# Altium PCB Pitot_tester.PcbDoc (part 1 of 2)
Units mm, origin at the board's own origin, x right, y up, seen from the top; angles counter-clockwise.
Board outline 94.03 x 112.06 mm, 2 copper layers (Top Layer, Bottom Layer), stack 1.658 mm thick; 71 components, 60 nets, 466 pads, 349 vias.
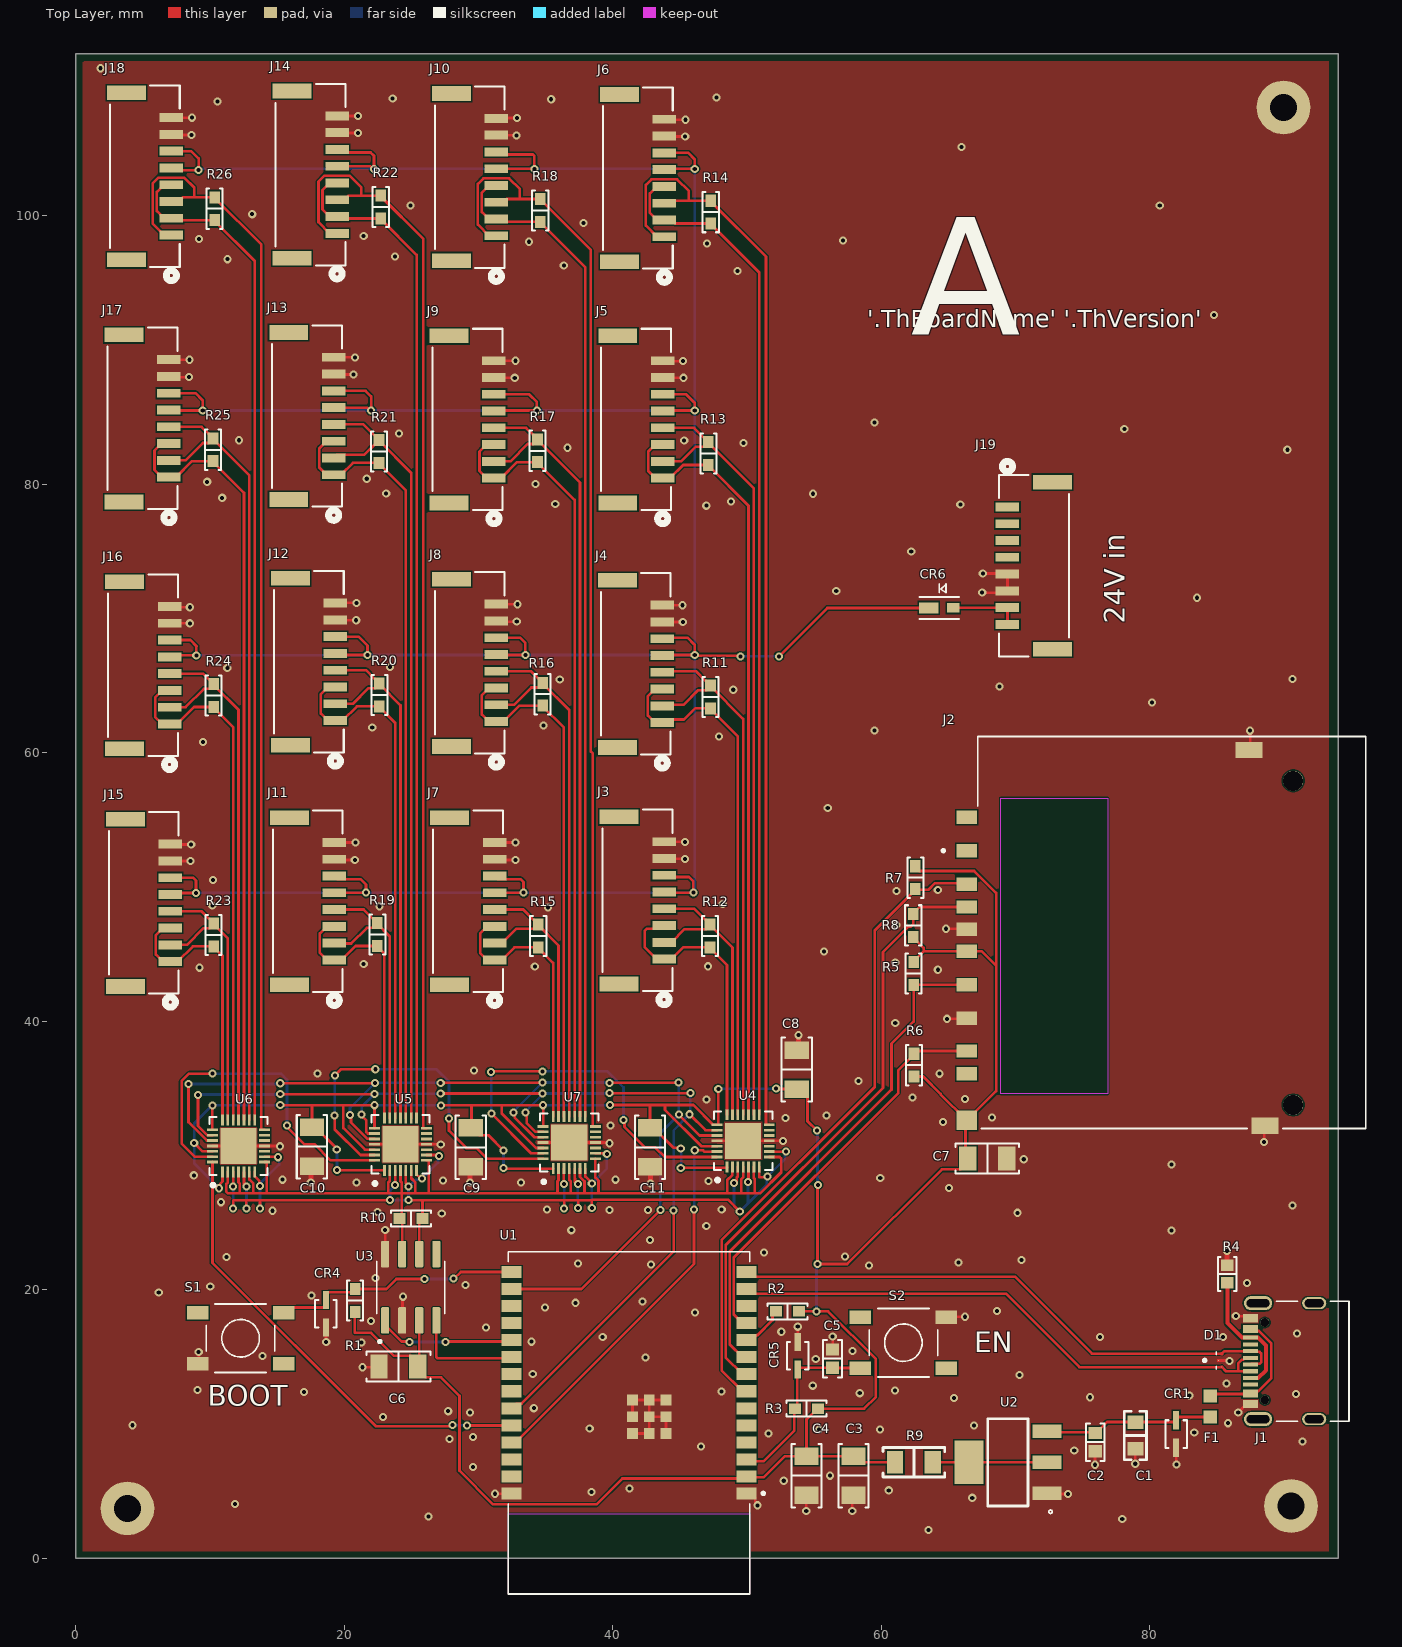
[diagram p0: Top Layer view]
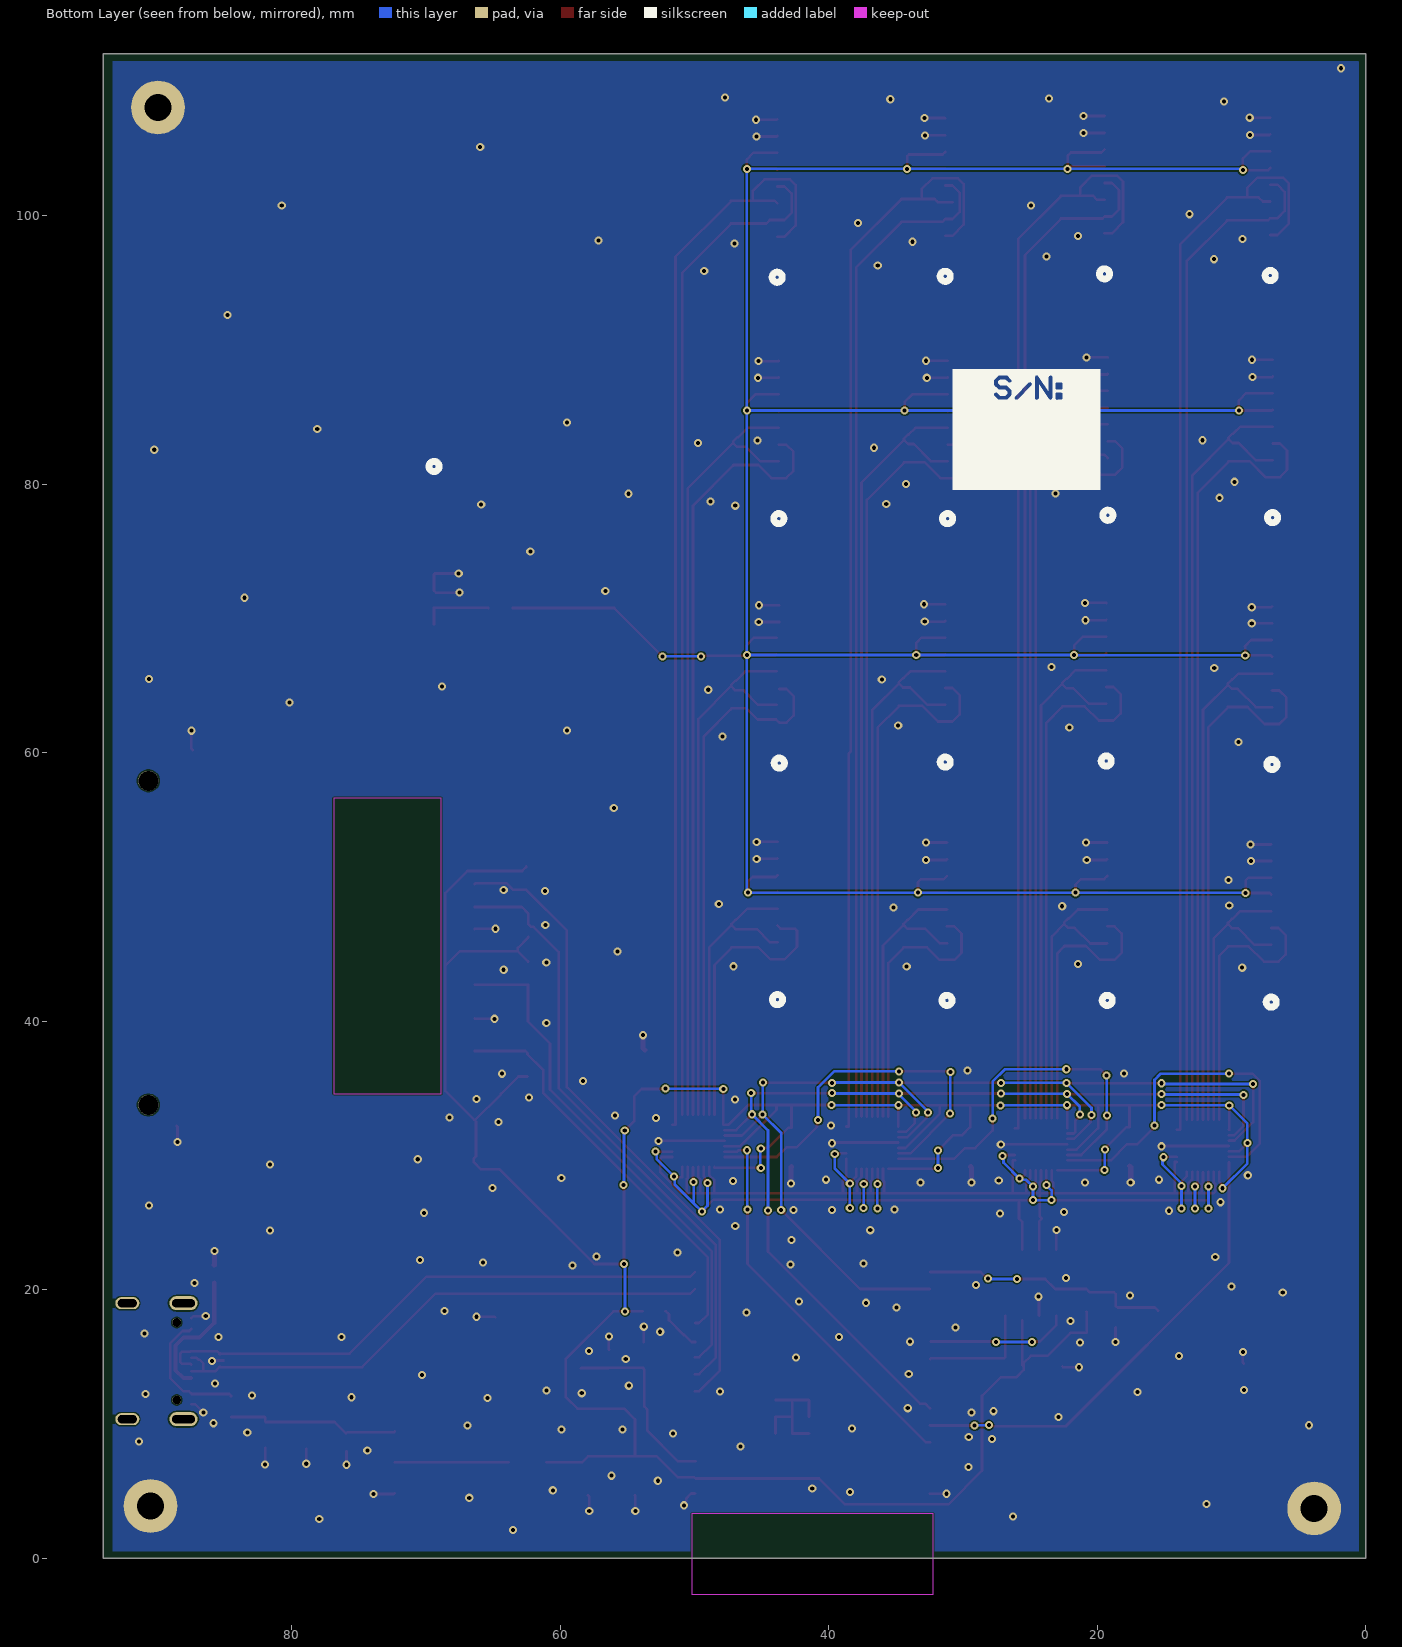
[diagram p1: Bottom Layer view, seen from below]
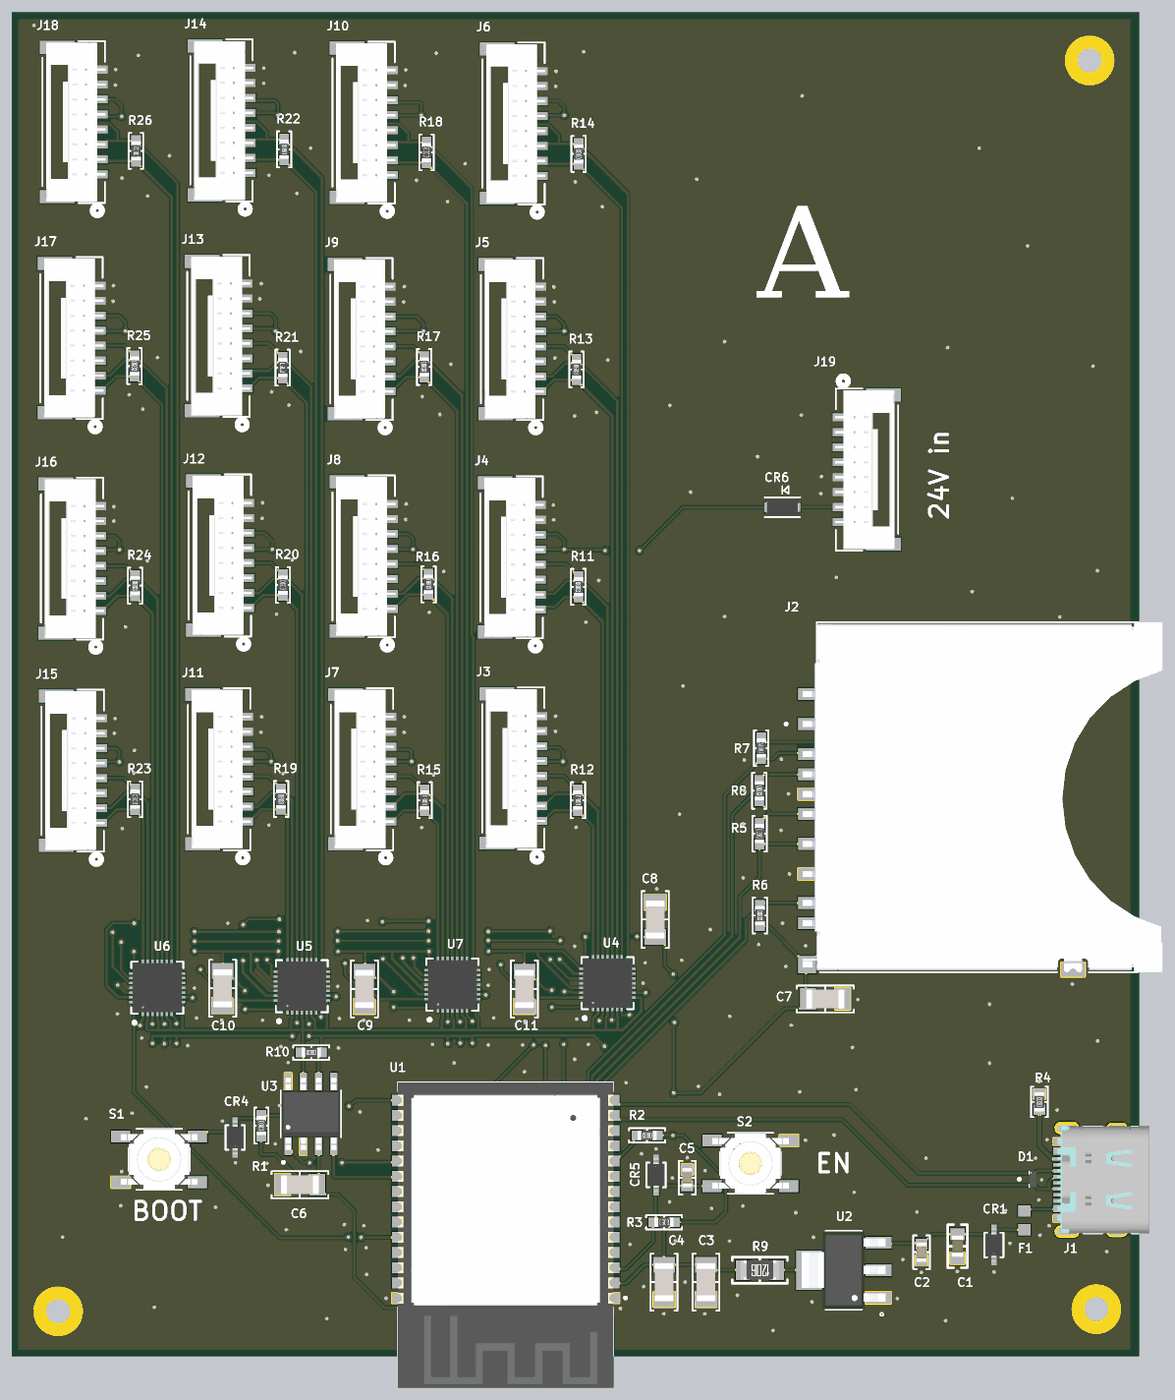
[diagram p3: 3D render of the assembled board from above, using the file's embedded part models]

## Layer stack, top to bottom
Top Solder: solder mask 0.0102, Solder Resist, Dk 3.5
Top Layer: signal copper 0.047
Dielectric 1: dielectric 1.564, FR-4, Dk 4.4
Bottom Layer: signal copper 0.047
Bottom Solder: solder mask 0.0102, Solder Resist, Dk 3.5

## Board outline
0,0 0,112.065 94.031,112.065 94.031,0

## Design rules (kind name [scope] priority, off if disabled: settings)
BoardOutlineClearance [All] p1: gap=0.4 ignorepadtopadclearanceinfootprint=FALSE
Clearance [All] p1: gap=0.1 ignorepadtopadclearanceinfootprint=FALSE
DiffPairsRouting [All] p1: maxlimit=0.5 minlimit=0.2 mostfreqgap=0.2 toplayer_minwidth=0.2 toplayer_maxwidth=0.2 toplayer_prefwidth=0.2 bottomlayer_minwidth=0.2 bottomlayer_maxwidth=0.2 bottomlayer_prefwidth=0.2 maxuncoupledlength=20
HoleSize [All] p1: absolutevalues=TRUE maxlimit=6.4 minlimit=0.2 maxpercent=80.000 minpercent=20.000
HoleToHoleClearance [All] p1: gap=0.45 allowstackedmicrovias=TRUE
MinimumAnnularRing [All] p1: minimumring=0.15
MinimumSolderMaskSliver [All] p1: minsoldermaskwidth=0.1
PolygonConnect [All] p1: connectstyle=Direct reliefconductorwidth=0.254 reliefentries=4 polygonreliefangle="90 Angle" airgapwidth=0.254
RoutingVias [All] p1: holewidth=0.3 width=0.6 viastyle="Through Hole" minholewidth=0.3 minwidth=0.5 maxholewidth=6.3 maxwidth=999
SilkToSilkClearance [All] p1: silktosilkclearance=0.2
SilkToSolderMaskClearance [IsPad] p1: minsilkscreentomaskgap=0.1 clearancetoexposedcopper=TRUE
SolderMaskExpansion SolderMaskExpansion_VIA [IsVia] p1: expansion=0.07 istentingtop=TRUE
SolderMaskExpansion [All] p2: expansion=0.07 istentingtop=FALSE
SupplyNets "Schematic Supply Nets_3" [InNet('+28')] p1: voltage=0.000
SupplyNets "Schematic Supply Nets_2" [InNet('+3.3')] p2: voltage=0.000
SupplyNets "Schematic Supply Nets_1" [InNet('+5')] p3: voltage=0.000
SupplyNets "Schematic Supply Nets" [InNet('GND')] p4: voltage=0.000
UnRoutedNet [All] p1: checkbadconnections=TRUE
Width [All] p1: maxlimit=999 minlimit=0.2 preferedwidth=0.2
23 further rules are at their usual default settings.

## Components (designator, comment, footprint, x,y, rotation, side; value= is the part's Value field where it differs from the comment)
C1 "10 µF" "MURATA GRM188 0603_1608" 78.932,9.142 r90 top
C2 "0.1 µF" "CAP 0603_1608" 75.932,8.642 r90 top
C3 "10 µF" "CAP 1206_3216 - 0.8MM" 57.932,6.142 r90 top
C4 "10 µF" "CAP 1206_3216 - 0.8MM" 54.432,6.142 r90 top
C5 "1 µF" "CAP 0603_1608" 56.363,14.859 r90 top
C6 "10 µF" "CAP 1206_3216 - 0.8MM" 24.028,14.275 r0 top
C7 "10 µF" "CAP 1206_3216 - 0.8MM" 67.894,29.769 r180 top
C8 "10 µF" "CAP 1206_3216 - 0.8MM" 53.696,36.398 r90 top
C9 "10 µF" "CAP 1206_3216 - 0.8MM" 29.413,30.607 r270 top
C10 "10 µF" "CAP 1206_3216 - 0.8MM" 17.577,30.658 r270 top
C11 "10 µF" "CAP 1206_3216 - 0.8MM" 42.774,30.607 r270 top
CR1 "PESD5V0U1BA_1" SOD323_NXP 81.966,9.246 r90 top
CR4 "PESD5V0U1BA_1" SOD323_NXP 18.618,18.212 r90 top
CR5 "PESD5V0U1BA_1" SOD323_NXP 53.772,15.088 r270 top
CR6 "MSS1P6-M389A" DIODE_MSP3V3_VIS 64.313,70.79 r0 top
D1 "ESD122DMYR" DIO_ESD122DMYR 85.242,14.732 r0 top
F1 "0603L100SLYR" FUSC1608X100N 84.506,11.301 r90 top
J1 "12402012E212A" AMPHENOL_12402012E212A 92.25,14.676 r90 top
J2 "GSD09002SDEU" AMPHENOL_GSD09002SDEU 90.68,46.612 r0 top
J3 "BM08B-GHS-TBT" CONN_BM08B-GHS-TBT_JST 41.838,49.003 r270 top
J4 "BM08B-GHS-TBT" CONN_BM08B-GHS-TBT_JST 41.707,66.624 r270 top
J5 "BM08B-GHS-TBT" CONN_BM08B-GHS-TBT_JST 41.737,84.835 r270 top
J6 "BM08B-GHS-TBT" CONN_BM08B-GHS-TBT_JST 41.859,102.819 r270 top
J7 "BM08B-GHS-TBT" CONN_BM08B-GHS-TBT_JST 29.21,48.946 r270 top
J8 "BM08B-GHS-TBT" CONN_BM08B-GHS-TBT_JST 29.342,66.7 r270 top
J9 "BM08B-GHS-TBT" CONN_BM08B-GHS-TBT_JST 29.164,84.835 r270 top
J10 "BM08B-GHS-TBT" CONN_BM08B-GHS-TBT_JST 29.342,102.889 r270 top
J11 "BM08B-GHS-TBT" CONN_BM08B-GHS-TBT_JST 17.272,48.946 r270 top
J12 "BM08B-GHS-TBT" CONN_BM08B-GHS-TBT_JST 17.348,66.777 r270 top
J13 "BM08B-GHS-TBT" CONN_BM08B-GHS-TBT_JST 17.226,85.089 r270 top
J14 "BM08B-GHS-TBT" CONN_BM08B-GHS-TBT_JST 17.475,103.073 r270 top
J15 "BM08B-GHS-TBT" CONN_BM08B-GHS-TBT_JST 5.055,48.819 r270 top
J16 "BM08B-GHS-TBT" CONN_BM08B-GHS-TBT_JST 5.004,66.523 r270 top
J17 "BM08B-GHS-TBT" CONN_BM08B-GHS-TBT_JST 4.953,84.912 r270 top
J18 "BM08B-GHS-TBT" CONN_BM08B-GHS-TBT_JST 5.131,102.946 r270 top
J19 "BM08B-GHS-TBT" CONN_BM08B-GHS-TBT_JST 71.374,73.939 r90 top
R1 "10 kOhms" "YAGEO RES 0603_1608" 20.803,19.202 r270 top
R2 "10 kOhms" "YAGEO RES 0603_1608" 53.01,18.39 r180 top
R3 "10 kOhms" "YAGEO RES 0603_1608" 54.432,11.142 r0 top
R4 "5.1 kOhms" "RES 0603_1608" 85.776,21.184 r90 top
R5 "10 kOhms" "YAGEO RES 0603_1608" 62.408,43.561 r90 top
R6 "10 kOhms" "YAGEO RES 0603_1608" 62.433,36.728 r270 top
R7 "10 kOhms" "YAGEO RES 0603_1608" 62.535,50.698 r90 top
R8 "10 kOhms" "YAGEO RES 0603_1608" 62.382,47.142 r270 top
R9 "500 mOhms" "RES 1206_3216" 62.432,7.142 r180 top
R10 "120 Ohms" "YAGEO RES 0603_1608" 24.968,25.298 r180 top
R11 "120 Ohms" "YAGEO RES 0603_1608" 47.269,64.16 r270 top
R12 "120 Ohms" "YAGEO RES 0603_1608" 47.244,46.355 r270 top
R13 "120 Ohms" "YAGEO RES 0603_1608" 47.117,82.296 r270 top
R14 "120 Ohms" "YAGEO RES 0603_1608" 47.295,100.279 r90 top
R15 "120 Ohms" "YAGEO RES 0603_1608" 34.442,46.355 r270 top
R16 "120 Ohms" "YAGEO RES 0603_1608" 34.773,64.364 r270 top
R17 "120 Ohms" "YAGEO RES 0603_1608" 34.392,82.499 r270 top
R18 "120 Ohms" "YAGEO RES 0603_1608" 34.595,100.406 r90 top
R19 "120 Ohms" "YAGEO RES 0603_1608" 22.454,46.457 r270 top
R20 "120 Ohms" "YAGEO RES 0603_1608" 22.606,64.313 r270 top
R21 "120 Ohms" "YAGEO RES 0603_1608" 22.581,82.448 r270 top
R22 "120 Ohms" "YAGEO RES 0603_1608" 22.708,100.66 r90 top
R23 "120 Ohms" "YAGEO RES 0603_1608" 10.262,46.431 r270 top
R24 "120 Ohms" "YAGEO RES 0603_1608" 10.262,64.262 r270 top
R25 "120 Ohms" "YAGEO RES 0603_1608" 10.211,82.575 r270 top
R26 "120 Ohms" "YAGEO RES 0603_1608" 10.338,100.533 r90 top
S1 "PTS525SM15SMTR2LFS" SW_PTS525SM15SMTR2LFS 12.268,16.383 r180 top
S2 "PTS525SM15SMTR2LFS" SW_PTS525SM15SMTR2LFS 61.646,16.053 r0 top
U1 "ESP32-C6-WROOM-1-N8" XCVR_ESP32-C6-WROOM-1-N8 41.208,10.076 r180 top
U2 "LD1117S33TR" SOT230P700X180-4N 69.432,7.142 r180 top
U3 "SN65HVD230DR" SOIC127P599X175-8N 24.943,20.181 r90 top
U4 "MAX14662ETI+T" 21-0139I_T2844-1C_MXM 49.708,31.09 r90 top
U5 "MAX14662ETI+T" 21-0139I_T2844-1C_MXM 24.181,30.836 r90 top
U6 "MAX14662ETI+T" 21-0139I_T2844-1C_MXM 12.116,30.709 r90 top
U7 "MAX14662ETI+T" 21-0139I_T2844-1C_MXM 36.754,30.963 r90 top

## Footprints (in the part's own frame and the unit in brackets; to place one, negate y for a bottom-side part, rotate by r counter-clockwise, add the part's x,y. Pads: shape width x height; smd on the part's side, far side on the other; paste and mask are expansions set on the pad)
21-0139I_T2844-1C_MXM [mil]
  rect 32x8 smd paste+0 mask+0: 1(-76.5,47.24) 2(-76.5,31.5) 3(-76.5,15.75) 4(-76.5,0) 5(-76.5,-15.75) 6(-76.5,-31.5) 7(-76.5,-47.24) 15(76.5,-47.24) 16(76.5,-31.5) 17(76.5,-15.75) 18(76.5,0) 19(76.5,15.75) 20(76.5,31.5) 21(76.5,47.24)
  rect 8x32 smd paste+0 mask+0: 8(-47.24,-76.5) 9(-31.5,-76.5) 10(-15.75,-76.5) 11(0,-76.5) 12(15.75,-76.5) 13(31.5,-76.5) 14(47.24,-76.5) 22(47.24,76.5) 23(31.5,76.5) 24(15.75,76.5) 25(0,76.5) 26(-15.75,76.5) 27(-31.5,76.5) 28(-47.24,76.5)
  rect 106x106 smd paste-53 mask+0: 29(0,0)
  silkscreen extent -120,-86 86,86, body extent -81,-81 81,81, height 32
AMPHENOL_12402012E212A [mm]
  rect 0.6x1.14 smd: A1_B12(-3.2,4.75) A4_B9(-2.4,4.75) B1_A12(3.2,4.75) B4_A9(2.4,4.75)
  rect 0.3x1.14 smd: A5(-1.25,4.75) A6(-0.25,4.75) A7(0.25,4.75) A8(1.25,4.75) B5(1.75,4.75) B6(0.75,4.75) B7(-0.75,4.75) B8(-1.75,4.75)
  oval 1.05x2.1 hole 0.6 slot 1.7 at 90 deg: SH1(-4.32,4.18) SH2(4.32,4.18)
  oval 0.9x1.8 hole 0.6 slot 1.4 at 90 deg: SH3(-4.32,0) SH4(4.32,0)
  round 0.65 hole 0.65 unplated: ""(-2.89,3.68) ""(2.89,3.68)
  silkscreen extent -4.47,-2.6 4.47,2.81, body extent -4.44,-2.66 4.49,4.94, height 3.25
AMPHENOL_GSD09002SDEU [mm]
  rect 1.5x1 smd: 1(-24.31,6.1) 2(-24.31,3.6) 3(-24.31,0.25) 4(-24.31,-1.4) 5(-24.31,-3.9) 6(-24.31,-6.4) 7(-24.31,-8.83) 8(-24.31,-10.53) 9(-24.31,8.6) 11(-24.31,1.9)
  rect 1.5x1.45 smd: 10(-24.31,-13.98)
  rect 2x1.2 smd: 12(-2.1,-14.4) 13(-3.3,13.6)
  round 1.5 hole 1.5 unplated: ""(0,-12.85) ""(0,11.3)
  Keep-Out Layer region: -13.8,-12 -21.8,-12 -21.8,10 -13.8,10
  silkscreen extent -26.16,-14.6 5.4,14.6, body extent -24.66,-14.6 5.4,14.6, height 2.7
"CAP 0603_1608" [mm] "Chip Capacitor, 2-Leads, Body 1.60x0.80mm, IPC Medium Density"
  rect 0.9x1 smd: 1(-0.675,0) 2(0.675,0)
  silkscreen extent -1.4,-0.7 1.4,0.7, body extent -0.8,-0.41 0.8,0.41, height 0.82
"CAP 1206_3216 - 0.8MM" [mm] "Chip Capacitor, 2-Leads, Body 3.25x1.60mm, IPC Medium Density"
  rect 1.3x1.8 smd: 1(-1.45,0) 2(1.45,0)
  silkscreen extent -2.37,-1.12 2.37,1.12, body extent -1.6,-0.8 1.6,0.8, height 0.8
CONN_BM08B-GHS-TBT_JST [mil]
  rect 26x69 smd paste+0 mask+0: 1(172.24,77.82) 2(123.03,77.82) 3(73.82,77.82) 4(24.61,77.82) 5(-24.61,77.82) 6(-73.82,77.82) 7(-123.03,77.82) 8(-172.24,77.82)
  rect 43x114 smd paste+0 mask+0: 9(-245.08,-54.07) 10(245.08,-54.07)
  silkscreen extent -266,-103 306,103, body extent -261,-90 261,105, height 159
DIO_ESD122DMYR [mm]
  rect 0.05x0.05 smd paste-1 mask+0: 1(-0.125,0) 2(0.125,-0.5) 3(0.125,0.5)
  Top Layer region: 0.183,0.599 0.185,0.599 0.188,0.598 0.19,0.598 0.193,0.597 0.195,0.596 0.198,0.595 0.2,0.593 0.202,0.592 0.204,0.59 0.206,0.589 0.208,0.587 0.21,0.585 0.212,0.583 0.214,0.581 0.215,0.579 0.217,0.577 0.218,0.575 0.22,0.573 0.221,0.57 0.222,0.568 0.223,0.565 0.223,0.563 0.224,0.56 0.224,0.558 0.225,0.555 0.225,0.553 0.225,0.55 0.225,0.45 0.225,0.447 0.225,0.445 0.224,0.442 0.224,0.44 0.223,0.437 0.223,0.435 0.222,0.432 0.221,0.43 0.22,0.427 0.218,0.425 0.217,0.423 0.215,0.421 0.214,0.419 0.212,0.417 0.21,0.415 0.208,0.413 0.206,0.411 0.204,0.41 0.202,0.408 0.2,0.407 0.198,0.405 0.195,0.404 0.193,0.403 0.19,0.402 0.188,0.402 0.185,0.401 0.183,0.401 0.18,0.4 0.07,0.4 0.067,0.401 0.065,0.401 0.062,0.402 0.06,0.402 0.057,0.403 0.055,0.404 0.052,0.405 0.05,0.407 0.048,0.408 0.046,0.41 0.044,0.411 0.042,0.413 0.04,0.415 0.038,0.417 0.036,0.419 0.035,0.421 0.033,0.423 0.032,0.425 0.03,0.427 0.029,0.43 0.028,0.432 0.027,0.435 0.027,0.437 0.026,0.44 0.026,0.442 0.025,0.445 0.025,0.447 0.025,0.45 0.025,0.55 0.025,0.553 0.025,0.555 0.026,0.558 0.026,0.56 0.027,0.563 0.027,0.565 0.028,0.568 0.029,0.57 0.03,0.573 0.032,0.575 0.033,0.577 0.035,0.579 0.036,0.581 0.038,0.583 0.04,0.585 0.042,0.587 0.044,0.589 0.046,0.59 0.048,0.592 0.05,0.593 0.052,0.595 0.055,0.596 0.057,0.597 0.06,0.598 0.062,0.598 0.065,0.599 0.067,0.599 0.07,0.6 0.18,0.6
  Top Layer region: 0.183,-0.401 0.185,-0.401 0.188,-0.402 0.19,-0.402 0.193,-0.403 0.195,-0.404 0.198,-0.405 0.2,-0.407 0.202,-0.408 0.204,-0.41 0.206,-0.411 0.208,-0.413 0.21,-0.415 0.212,-0.417 0.214,-0.419 0.215,-0.421 0.217,-0.423 0.218,-0.425 0.22,-0.427 0.221,-0.43 0.222,-0.432 0.223,-0.435 0.223,-0.437 0.224,-0.44 0.224,-0.442 0.225,-0.445 0.225,-0.447 0.225,-0.45 0.225,-0.55 0.225,-0.553 0.225,-0.555 0.224,-0.558 0.224,-0.56 0.223,-0.563 0.223,-0.565 0.222,-0.568 0.221,-0.57 0.22,-0.573 0.218,-0.575 0.217,-0.577 0.215,-0.579 0.214,-0.581 0.212,-0.583 0.21,-0.585 0.208,-0.587 0.206,-0.589 0.204,-0.59 0.202,-0.592 0.2,-0.593 0.198,-0.595 0.195,-0.596 0.193,-0.597 0.19,-0.598 0.188,-0.598 0.185,-0.599 0.183,-0.599 0.18,-0.6 0.07,-0.6 0.067,-0.599 0.065,-0.599 0.062,-0.598 0.06,-0.598 0.057,-0.597 0.055,-0.596 0.052,-0.595 0.05,-0.593 0.048,-0.592 0.046,-0.59 0.044,-0.589 0.042,-0.587 0.04,-0.585 0.038,-0.583 0.036,-0.581 0.035,-0.579 0.033,-0.577 0.032,-0.575 0.03,-0.573 0.029,-0.57 0.028,-0.568 0.027,-0.565 0.027,-0.563 0.026,-0.56 0.026,-0.558 0.025,-0.555 0.025,-0.553 0.025,-0.55 0.025,-0.45 0.025,-0.447 0.025,-0.445 0.026,-0.442 0.026,-0.44 0.027,-0.437 0.027,-0.435 0.028,-0.432 0.029,-0.43 0.03,-0.427 0.032,-0.425 0.033,-0.423 0.035,-0.421 0.036,-0.419 0.038,-0.417 0.04,-0.415 0.042,-0.413 0.044,-0.411 0.046,-0.41 0.048,-0.408 0.05,-0.407 0.052,-0.405 0.055,-0.404 0.057,-0.403 0.06,-0.402 0.062,-0.402 0.065,-0.401 0.067,-0.401 0.07,-0.4 0.18,-0.4
  Top Layer region: -0.067,0.099 -0.065,0.099 -0.062,0.098 -0.06,0.098 -0.057,0.097 -0.055,0.096 -0.052,0.095 -0.05,0.093 -0.048,0.092 -0.046,0.09 -0.044,0.089 -0.042,0.087 -0.04,0.085 -0.038,0.083 -0.036,0.081 -0.035,0.079 -0.033,0.077 -0.032,0.075 -0.03,0.073 -0.029,0.07 -0.028,0.068 -0.027,0.065 -0.027,0.063 -0.026,0.06 -0.026,0.058 -0.025,0.055 -0.025,0.053 -0.025,0.05 -0.025,-0.05 -0.025,-0.053 -0.025,-0.055 -0.026,-0.058 -0.026,-0.06 -0.027,-0.063 -0.027,-0.065 -0.028,-0.068 -0.029,-0.07 -0.03,-0.073 -0.032,-0.075 -0.033,-0.077 -0.035,-0.079 -0.036,-0.081 -0.038,-0.083 -0.04,-0.085 -0.042,-0.087 -0.044,-0.089 -0.046,-0.09 -0.048,-0.092 -0.05,-0.093 -0.052,-0.095 -0.055,-0.096 -0.057,-0.097 -0.06,-0.098 -0.062,-0.098 -0.065,-0.099 -0.067,-0.099 -0.07,-0.1 -0.18,-0.1 -0.183,-0.099 -0.185,-0.099 -0.188,-0.098 -0.19,-0.098 -0.193,-0.097 -0.195,-0.096 -0.198,-0.095 -0.2,-0.093 -0.202,-0.092 -0.204,-0.09 -0.206,-0.089 -0.208,-0.087 -0.21,-0.085 -0.212,-0.083 -0.214,-0.081 -0.215,-0.079 -0.217,-0.077 -0.218,-0.075 -0.22,-0.073 -0.221,-0.07 -0.222,-0.068 -0.223,-0.065 -0.223,-0.063 -0.224,-0.06 -0.224,-0.058 -0.225,-0.055 -0.225,-0.053 -0.225,-0.05 -0.225,0.05 -0.225,0.053 -0.225,0.055 -0.224,0.058 -0.224,0.06 -0.223,0.063 -0.223,0.065 -0.222,0.068 -0.221,0.07 -0.22,0.073 -0.218,0.075 -0.217,0.077 -0.215,0.079 -0.214,0.081 -0.212,0.083 -0.21,0.085 -0.208,0.087 -0.206,0.089 -0.204,0.09 -0.202,0.092 -0.2,0.093 -0.198,0.095 -0.195,0.096 -0.193,0.097 -0.19,0.098 -0.188,0.098 -0.185,0.099 -0.183,0.099 -0.18,0.1 -0.07,0.1
  silkscreen extent -1.25,-0.65 -0.3,0.65, body extent -0.3,-0.65 0.3,0.65, height 0.4
DIODE_MSP3V3_VIS [mil]
  rect 57x33 smd paste+0 mask+0: 1(-30.5,0)
  rect 36x28 smd paste+0 mask+0: 2(41,0)
  silkscreen extent -58,-32 58,70, body extent -53,-27 53,27, height 29
FUSC1608X100N [mm]
  rect 0.95x1.02 smd: 1(-0.785,0) 2(0.785,0)
"MURATA GRM188 0603_1608" [mm] "Chip Capacitor, 2-Leads, Body 1.60x0.80mm"
  rect 1x1.2 smd: 1(-1,0) 2(1,0)
  silkscreen extent -1.8,-0.83 1.8,0.83, body extent -0.9,-0.5 0.9,0.5, height 1
"RES 0603_1608" [mm] "Chip Resistor, 2-Leads, Body 1.60x0.80mm, IPC Medium Density"
  rect 0.85x0.95 smd: 1(-0.65,0) 2(0.65,0)
  silkscreen extent -1.27,-0.7 1.27,0.7, body extent -0.8,-0.4 0.8,0.4, height 0.45
"RES 1206_3216" [mm] "Chip Resistor, 2-Leads, Body 3.13x1.55mm, IPC Medium Density"
  rect 1.2x1.65 smd: 1(-1.4,0) 2(1.4,0)
  silkscreen extent -2.3,-1.1 2.3,1.1, body extent -1.6,-0.8 1.6,0.8, height 0.6
SOD323_NXP [mil]
  rect 53.5x18 smd paste+0 mask+0: 1(-40.25,0) 2(40.25,0)
  silkscreen extent -40,-32 40,32, body extent -53,-26 53,26, height 43
SOIC127P599X175-8N [mm]
  rrect25% 1.97x0.6 smd: 1(-2.47,1.905) 2(-2.47,0.635) 3(-2.47,-0.635) 4(-2.47,-1.905) 5(2.47,-1.905) 6(2.47,-0.635) 7(2.47,0.635) 8(2.47,1.905)
  silkscreen extent -4.14,-2.52 1.95,2.52, body extent -3,-2.45 3,2.45, height 1.75
SOT230P700X180-4N [mm]
  rect 2.15x1 smd: 1(-2.9,2.3) 2(-2.9,0) 3(-2.9,-2.3)
  rect 2.15x3.25 smd: 4(2.9,0)
  silkscreen extent -3.3,-3.25 1.5,3.81, body extent -3.5,-3.25 3.5,3.25, height 1.8
SW_PTS525SM15SMTR2LFS [mm]
  rect 1.6x1 smd: 1(-3.2,1.9) 2(3.2,1.9) 3(-3.2,-1.9) 4(3.2,-1.9)
  silkscreen extent -2.55,-2.55 2.55,2.55, body extent -3.2,-2.55 3.2,2.55, height 1.6
XCVR_ESP32-C6-WROOM-1-N8 [mm]
  rect 1.5x0.9 smd: 1(-8.75,5.26) 2(-8.75,3.99) 3(-8.75,2.72) 4(-8.75,1.45) 5(-8.75,0.18) 6(-8.75,-1.09) 7(-8.75,-2.36) 8(-8.75,-3.63) 9(-8.75,-4.9) 10(-8.75,-6.17) 11(-8.75,-7.44) 12(-8.75,-8.71) 13(-8.75,-9.98) 14(-8.75,-11.25) 15(8.75,-11.25) 16(8.75,-9.98) 17(8.75,-8.71) 18(8.75,-7.44) 19(8.75,-6.17) 20(8.75,-4.9) 21(8.75,-3.63) 22(8.75,-2.36) 23(8.75,-1.09) 24(8.75,0.18) 25(8.75,1.45) 26(8.75,2.72) 27(8.75,3.99) 28(8.75,5.26)
  rect 0.8x0.8 smd: 29(-2.755,-0.46) 29(-2.755,0.79) 29(-2.755,-1.71) 29(-1.505,0.79) 29(-1.505,-0.46) 29(-1.505,-1.71) 29(-0.255,0.79) 29(-0.255,-0.46) 29(-0.255,-1.71)
  Keep-Out Layer region: 9,6.75 -9,6.75 -9,12.75 9,12.75
  silkscreen extent -10.1,-12.75 9,12.75, body extent -9,-12.75 9,12.75, height 3.25
"YAGEO RES 0603_1608" [mm] "Chip Resistor, 2-Leads, Body 1.60x0.80mm"
  rect 0.9x0.8 smd: 1(-0.85,0) 2(0.85,0)
  silkscreen extent -1.5,-0.6 1.5,0.6, body extent -0.8,-0.4 0.8,0.4, height 0.45

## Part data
C1: library part GRM188R60J106ME47D, "CAP CER 10UF 6.3V X5R 0603", Device Package="0603 (1608 Metric)", manufacturer="Murata Electronics", Operating Temperature="-55°C ~ 85°C", Supplier Part Number 1=490-3896-1-ND, Temperature Coefficient=X5R, Tolerance=±20%, Voltage - Rated=6.3V
C2: library part 6R3X14W104MV4T, "CAP CER 0.1UF 6.3V X7R 0603", Device Package="0603 (1608 Metric)", manufacturer="Johanson Dielectrics Inc.", Operating Temperature="-55°C ~ 125°C", Supplier Part Number 1=709-1009-1-ND, Temperature Coefficient=X7R, Tolerance=±20%, Voltage - Rated=6.3V
C3 C4 C6 C7 C8 C9 C10 C11: library part EMK316BJ106MD-T, "CAP CER 10UF 16V X5R 1206", Device Package="1206 (3216 Metric)", manufacturer="Taiyo Yuden", Operating Temperature="-55°C ~ 85°C", Supplier Part Number 1=587-4881-1-ND, Temperature Coefficient=X5R, Tolerance=±20%, Voltage - Rated=16V
C5: library part C0603C105K4RACAUTO, "CAP CER 1UF 16V X7R 0603", Device Package="0603 (1608 Metric)", manufacturer=KEMET, Operating Temperature="-55°C ~ 125°C", Ratings=AEC-Q200, Supplier Part Number 1=399-17704-1-ND, Temperature Coefficient=X7R, Tolerance=±10%, Voltage - Rated=16V
CR1 CR4 CR5: "No Description Available", Mfr_Name=NXP
CR6: "No Description Available", Mfr_Name=Vishay
D1: "Dual 0.2-pF, Â±3.6-V, Â±17-kV ESD protection diode for USB Type-C and HDMI 2.0", Package="X2SON-3 Texas Instruments"
F1: Package=None
J1: "USB2.0, Type C, Top mount, CH 1.68mm, Dual Row SMT", Package=None
J2: "Micro SD and SD Card Sockets, Input Output Connectors, SD Socket,9Position Push Push 15Î¼in Gold", Package=None
J3 J4 J5 J6 J7 J8 J9 J10 J11 J12 J13 J14 J15 J16 J17 J18 J19: "No Description Available", Mfr_Name=JST
R1 R2 R3 R5 R6 R7 R8: library part RT0603DRD0710KL, "RES SMD 10K OHM 0.5% 1/10W 0603", Device Package="0603 (1608 Metric)", manufacturer=Yageo, Operating Temperature="-55°C ~ 155°C", Power (Watts)="0.1W, 1/10W", Supplier Device Package=0603, Supplier Part Number 1=311-10KDCT-ND, Temperature Coefficient=±25ppm/°C, Tolerance=±0.5%
R4: library part TNPW06035K10BYEN, "RES 5.1K OHM 0.1% 1/10W 0603", Device Package="0603 (1608 Metric)", manufacturer="Vishay Dale", Operating Temperature="-55°C ~ 155°C", Power (Watts)="0.125W, 1/8W", Ratings=AEC-Q200, Supplier Device Package=0603, Supplier Part Number 1=541-9831-1-ND, Temperature Coefficient=±10ppm/°C, Tolerance=±0.1%
R9: library part CSR1206FTR500, "RES 0.5 OHM 1% 1/2W 1206", Device Package="1206 (3216 Metric)", manufacturer="Stackpole Electronics Inc", Operating Temperature="-55°C ~ 155°C", Power (Watts)="0.5W, 1/2W", Supplier Device Package=1206, Supplier Part Number 1=CSR1206FTR500CT-ND, Temperature Coefficient=±100ppm/°C, Tolerance=±1%
R10 R11 R12 R13 R14 R15 R16 R17 R18 R19 R20 R21 R22 R23 R24 R25 R26: library part AC0603JR-07120RL, "RES SMD 120 OHM 5% 1/10W 0603", Device Package="0603 (1608 Metric)", manufacturer=Yageo, Operating Temperature="-55°C ~ 155°C", Power (Watts)="0.1W, 1/10W", Ratings=AEC-Q200, Supplier Device Package=0603, Supplier Part Number 1=YAG3639CT-ND, Temperature Coefficient=±100ppm/°C, Tolerance=±5%
S1 S2: "Tactile Switch SPST-NO Top Actuated Surface Mount", Package="Tactile Switch CK"
U1: "Multiprotocol Modules ESP32-C6 module, Wi-Fi 6 in 2.4 GHz band, Bluetooth 5, Zigbee 3.0 and Thread. ESP34-WROOM Compatible - ENGINEERING SAMPLE", Package="SMD-28 Espressif Systems"
U2: "Linear Voltage Regulator IC Positive Fixed 1 Output 800mA SOT-223", Package="TO-261-4 STMicroelectronics"
U3: "3.3 V CAN Transceiver with Standby Mode", Package="SOIC-8 Texas Instruments"
U4 U5 U6 U7: "No Description Available", Mfr_Name="Analog Devices / Maxim Integrated"

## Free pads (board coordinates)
  round 4 hole 2: 5(3.835,3.708) 5(89.967,108.077) 5(90.526,3.886)

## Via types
v1: diameter 0.61, hole 0.305, Top Layer to Bottom Layer, tented both sides, 187 vias
v2: diameter 0.6, hole 0.3, Top Layer to Bottom Layer, tented both sides, 162 vias

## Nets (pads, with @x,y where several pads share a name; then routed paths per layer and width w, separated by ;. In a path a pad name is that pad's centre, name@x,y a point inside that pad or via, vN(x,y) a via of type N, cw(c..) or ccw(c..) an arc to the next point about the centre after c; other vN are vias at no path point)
+3.3: C3.2 C4.2 C6.2 C7.2 C8.1 C9.1 C10.1 C11.1 J2.4 J2.10 R1.2 R2.1 R3.2 R5.2 R6.2 R7.2 R8.2 R9.2 U1.2 U3.3 U4.1 U4.22 U4.26 U5.1 U5.22 U5.26 U6.1 U6.22 U6.26 U7.1 U7.22 U7.26 | length 253.7
  Top Layer w0.2: v2(8.814,30.937) 9.441,30.31 9.866,30.31 9.868,30.309 U6.26@10.173,30.309 ; v2(10.16,33.731) 10.16,31.91 10.162,31.909 U6.22@10.173,31.909 ; v2(10.673,27.559) 10.749,27.636 10.749,27.893 10.916,28.059 U6.1@10.916,28.765 ; v2(15.223,33.757) 15.235,33.744 17.587,33.744 ; v2(19.431,30.455) 19.431,30.504 17.827,32.108 C10.1@17.577,32.108 17.587,32.118 17.587,33.744 ; v2(19.456,28.905) 19.469,28.892 U5.1@22.981,28.892 ; R1.2@20.803,18.352 20.771,18.321 20.771,16.783 21.995,16.783 23.704,15.075 24.928,15.075 25.478,14.525 C6.2@25.478,14.275 ; U5.26@22.238,30.436 21.533,30.436 19.922,32.047 19.922,33.727 19.939,33.744 ; U5.22@22.238,32.036 v2(22.238,33.744) 19.939,33.744 ; U3.3@25.578,17.711 25.578,14.374 C6.2@25.478,14.275 ; v2(27.203,33.731) 29.464,33.731 ; v2(31.852,29.083) 31.915,29.019 U7.1@35.554,29.019 ; v2(31.852,30.378) 30.723,31.507 30.065,31.507 29.464,32.108 29.464,33.731 ; U7.26@34.811,30.563 34.809,30.564 34.282,30.564 31.725,33.122 31.725,33.731 ; U7.22@34.811,32.163 v2(34.811,33.744) 34.798,33.731 31.725,33.731 ; v2(39.776,33.757) 42.723,33.757 ; v2(45.06,29.083) 48.506,29.083 48.508,29.085 U4.1@48.508,29.146 ; v2(45.06,30.505) 44.983,30.582 44.499,30.582 43.024,32.057 C11.1@42.774,32.057 42.774,33.706 42.723,33.757 ; U4.26@47.765,30.69 46.603,30.69 43.891,33.401 43.891,33.757 ; v2(47.854,34.95) 47.854,32.291 47.852,32.29 U4.22@47.765,32.29 47.46,32.29 45.993,33.757 43.891,33.757 ; v2(52.172,34.976) 52.199,34.948 C8.1@53.696,34.948 53.946,34.948 54.496,34.398 54.496,32.55 v2(55.194,31.852) ; R2.1@53.86,18.39 v2(55.169,18.39) 56.032,18.39 59.588,14.834 59.588,12.015 58.715,11.142 R3.2@55.282,11.142 55.232,11.142 54.432,10.342 54.432,9.5 C4.2@54.432,7.592 ; v2(55.296,27.813) 55.245,27.762 v2(55.245,21.92) 57.457,21.92 64.506,28.969 65.894,28.969 66.444,29.519 C7.2@66.444,29.769 66.269,29.944 66.269,32.53 J2.10@66.37,32.632 ; R9.2@61.032,7.142 58.382,7.142 C3.2@57.932,7.592 C4.2@54.432,7.592 ; R8.2@62.382,46.292 62.382,46.242 63.159,45.466 63.159,45.212 ; R5.2@62.408,44.411 62.408,44.461 63.159,45.212 ; R6.2@62.433,35.878 63.124,35.878 64.422,34.58 64.422,34.555 66.345,32.632 J2.10@66.37,32.632 ; R7.2@62.535,51.548 62.535,51.498 62.835,51.198 66.917,51.198 68.555,49.56 68.555,44.145 ; 17.587,33.744 19.939,33.744 ; C6.2@25.478,14.275 25.478,14.025 26.028,13.475 27.192,13.475 28.575,12.092 28.575,6.516 31.076,4.016 38.784,4.016 40.71,5.942 49.927,5.942 50.026,6.04 51.248,6.04 52.8,7.592 C4.2@54.432,7.592 ; 29.464,33.731 31.725,33.731 ; 42.723,33.757 43.891,33.757 ; 63.159,45.212 J2.4@66.37,45.212 67.488,45.212 68.555,44.145 ; J2.10@66.37,32.632 66.395,32.632 68.555,34.791 68.555,44.145
  Bottom Layer w0.2: v2(10.673,27.559) 10.668,27.559 8.814,29.413 v2(8.814,30.937) 8.814,32.385 10.185,33.757 10.198,33.744 15.21,33.744 v2(15.223,33.757) ; v2(19.431,30.455) 19.444,30.442 19.444,28.918 v2(19.456,28.905) ; v2(22.238,33.744) 27.191,33.744 v2(27.203,33.731) ; v2(31.852,29.083) v2(31.852,30.378) ; v2(34.811,33.744) 39.764,33.744 v2(39.776,33.757) ; v2(45.06,29.083) 45.099,29.123 45.099,30.466 v2(45.06,30.505) ; v2(47.854,34.95) 47.879,34.976 v2(52.172,34.976) ; v2(55.169,18.39) 55.169,21.844 v2(55.245,21.92) ; v2(55.194,31.852) 55.245,31.801 55.245,27.864 v2(55.296,27.813)
+5: C1.2 C2.2 CR1.2 F1.1 U2.3 | length 12.9
  Top Layer w0.2: U2.3@72.332,9.442 72.394,9.379 75.869,9.379 C2.2@75.932,9.317 75.982,9.317 76.807,10.142 C1.2@78.932,10.142 81.928,10.142 81.966,10.18 CR1.2@81.966,10.268 81.966,10.477 82.004,10.516 F1.1@84.506,10.516
+28: CR6.1 J3.5 J3.6 J4.5 J4.6 J5.5 J5.6 J6.5 J6.6 J7.5 J7.6 J8.5 J8.6 J9.5 J9.6 J10.5 J10.6 J11.5 J11.6 J12.5 J12.6 J13.5 J13.6 J14.5 J14.6 J15.5 J15.6 J16.5 J16.6 J17.5 J17.6 J18.5 J18.6 | length 313.6
  Top Layer w0.2: J17.5@6.93,85.537 6.97,85.496 v2(9.449,85.496) 9.449,86.258 8.92,86.787 J17.6@6.93,86.787 ; J16.5@6.98,67.148 7.092,67.259 v2(8.966,67.259) 8.966,67.92 8.985,67.938 8.526,68.398 J16.6@6.98,68.398 ; J15.5@7.031,49.444 7.143,49.555 v2(8.941,49.555) 8.941,50.47 8.717,50.694 J15.6@7.031,50.694 ; J18.5@7.107,103.571 7.275,103.403 v2(9.144,103.403) 9.144,104.267 8.59,104.821 J18.6@7.107,104.821 ; J13.5@19.202,85.714 21.67,85.714 21.888,85.496 v2(21.996,85.496) 21.996,86.538 21.57,86.964 J13.6@19.202,86.964 ; J11.5@19.249,49.571 19.259,49.581 v2(21.615,49.581) 21.615,50.175 21.2,50.591 19.479,50.591 J11.6@19.249,50.821 ; J12.5@19.325,67.402 19.442,67.285 v2(21.717,67.285) 21.717,67.996 21.061,68.652 J12.6@19.325,68.652 ; J14.5@19.452,103.698 21.898,103.698 22.091,103.505 v2(22.2,103.505) 22.2,104.48 21.962,104.718 19.682,104.718 J14.6@19.452,104.948 ; J9.5@31.14,85.46 31.177,85.496 v2(34.341,85.496) 34.341,86.131 33.762,86.71 J9.6@31.14,86.71 ; J7.5@31.187,49.571 31.197,49.581 v2(33.35,49.581) 33.35,50.368 33.128,50.591 31.417,50.591 J7.6@31.187,50.821 ; J8.5@31.318,67.325 31.358,67.285 v2(33.477,67.285) 33.477,68.174 33.076,68.575 J8.6@31.318,68.575 ; J10.5@31.318,103.514 31.327,103.505 v2(34.15,103.505) 34.15,104.455 34.033,104.572 31.511,104.572 J10.6@31.318,104.764 ; J5.5@43.713,85.46 43.75,85.496 v2(46.101,85.496) 46.101,86.055 45.446,86.71 J5.6@43.713,86.71 ; J3.5@43.815,49.628 43.862,49.581 v2(45.999,49.581) 45.999,50.419 45.669,50.749 43.944,50.749 J3.6@43.815,50.878 ; J6.5@43.836,103.444 43.897,103.505 v2(46.101,103.505) 46.101,104.216 45.623,104.694 J6.6@43.836,104.694 ; J4.5@43.891,67.325 43.931,67.285 v2(46.101,67.285) ; J4.6@43.891,68.575 45.548,68.575 46.101,68.021 v2(46.101,67.285) ; v2(49.505,67.183) 49.454,67.234 46.152,67.234 v2(46.101,67.285) ; v2(52.375,67.183) 55.982,70.79 CR6.1@63.538,70.79
  Bottom Layer w0.2: v2(8.941,49.555) 8.966,49.581 v2(21.615,49.581) v2(33.35,49.581) v2(45.999,49.581) 46.101,49.682 v2(46.101,67.285) ; v2(8.966,67.259) 8.979,67.272 21.704,67.272 v2(21.717,67.285) v2(33.477,67.285) v2(46.101,67.285) ; v2(9.144,103.403) 9.246,103.505 v2(22.2,103.505) v2(34.15,103.505) v2(46.101,103.505) v2(46.101,85.496) ; v2(9.449,85.496) v2(21.996,85.496) v2(34.341,85.496) v2(46.101,85.496) ; v2(49.505,67.183) v2(52.375,67.183) ; v2(46.101,67.285) v2(46.101,85.496)
Boot: CR4.2 R1.1 S1.3 U1.15 | length 18.7
  Top Layer w0.2: S1.3@15.469,18.44 15.697,18.669 18.49,18.669 18.618,18.798 18.618,19.683 18.747,19.812 20.562,19.812 R1.1@20.803,20.052 23.123,20.052 23.873,20.803 v2(25.984,20.803) ; v2(28.118,20.828) 28.177,20.828 28.675,21.326 U1.15@32.458,21.326
  Bottom Layer w0.2: v2(25.984,20.803) 28.092,20.803 v2(28.118,20.828)
CAN_RX: U1.20 U3.4 | length 8.7
  Top Layer w0.2: U3.4@26.848,18.053 26.848,14.986 26.941,14.893 32.367,14.893 U1.20@32.428,14.833
CAN_TX: U1.19 U3.1 | length 10.6
  Top Layer w0.2: U3.1@23.038,18.053 23.038,17.368 24.26,16.146 24.799,16.146 v2(24.841,16.104) ; v2(27.534,16.104) 27.576,16.146 32.385,16.146 U1.19@32.389,16.141
  Bottom Layer w0.2: v2(24.841,16.104) v2(27.534,16.104)
CANH: R10.2 U3.7 U4.2 U4.4 U4.6 U4.8 U5.2 U5.4 U5.6 U5.8 U6.2 U6.4 U6.6 U6.8 U7.2 U7.4 U7.6 U7.8 | length 78.2
  Top Layer w0.2: U6.2@11.316,28.765 11.316,28 11.209,27.893 11.209,27.295 11.327,27.178 12.209,27.178 ; U6.4@12.116,28.765 12.116,27.987 12.209,27.893 12.209,27.178 ; U6.6@12.916,28.765 12.917,28.764 12.917,28.201 13.216,27.903 13.216,27.178 ; U6.8@14.059,29.509 14.214,29.509 14.216,29.507 14.216,27.178 ; U5.2@23.381,28.892 23.381,28.101 23.274,27.995 23.274,27.178 ; U5.4@24.181,28.892 24.181,28.088 24.274,27.995 24.274,27.178 ; U3.7@24.308,22.993 24.308,25.109 R10.2@24.118,25.298 24.274,25.455 24.274,27.178 ; U5.6@24.981,28.892 24.982,28.891 24.982,28.303 25.29,27.995 25.29,27.178 ; U5.8@26.124,29.636 26.279,29.636 26.281,29.634 26.281,27.178 ; U7.2@35.954,29.019 35.954,28.152 35.873,28.071 35.873,27.178 ; U7.4@36.754,29.019 36.754,28.19 36.873,28.071 36.873,27.178 ; U7.6@37.554,29.019 37.554,28.406 37.889,28.071 37.889,27.178 ; U7.8@38.697,29.763 38.697,28.355 38.93,28.122 38.93,27.178 ; U4.2@48.908,29.146 48.906,29.145 48.906,28.557 48.522,28.173 48.522,27.178 ; U4.4@49.708,29.146 49.708,28.368 49.563,28.223 49.563,27.178 ; U4.6@50.508,29.146 50.508,28.33 50.563,28.274 50.563,27.178 ; U4.8@51.651,29.89 52.429,29.89 52.546,29.772 52.546,28.751 50.974,27.178 50.563,27.178 ; 12.209,27.178 13.216,27.178 ; 13.216,27.178 14.216,27.178 ; 14.216,27.178 23.274,27.178 ; 23.274,27.178 24.274,27.178 ; 24.274,27.178 25.29,27.178 ; 25.29,27.178 26.281,27.178 ; 26.281,27.178 35.873,27.178 ; 35.873,27.178 36.873,27.178 ; 36.873,27.178 37.889,27.178 ; 37.889,27.178 38.93,27.178 ; 38.93,27.178 48.522,27.178 ; 48.522,27.178 49.563,27.178 ; 49.563,27.178 50.563,27.178
CANH_1: J3.1 J3.3 R12.2 U4.21 | length 21.4
  Top Layer w0.2: J3.3@43.815,47.128 43.585,46.898 42.529,46.898 42.367,46.736 42.367,45.529 43.269,44.628 J3.1@43.815,44.628 44.361,44.628 45.238,45.505 R12.2@47.244,45.505 47.244,45.455 48.508,44.191 U4.21@48.508,33.033
CANH_2: J4.1 J4.3 R11.2 U4.19 | length 39.2
  Top Layer w0.2: J4.3@43.683,64.749 43.137,64.749 42.607,64.219 42.607,62.779 43.137,62.249 J4.1@43.683,62.249 43.914,62.479 45.299,62.479 46.13,63.31 R11.2@47.269,63.31 47.269,63.26 49.308,61.222 U4.19@49.308,33.033
CANH_3: J5.1 J5.3 R13.2 U4.17 | length 57.5
  Top Layer w0.2: J5.3@43.713,82.96 43.167,82.96 42.637,82.43 42.637,80.99 43.167,80.46 J5.1@43.713,80.46 44.259,80.46 45.245,81.446 R13.2@47.117,81.446 47.117,81.396 50.108,78.405 U4.17@50.108,33.033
